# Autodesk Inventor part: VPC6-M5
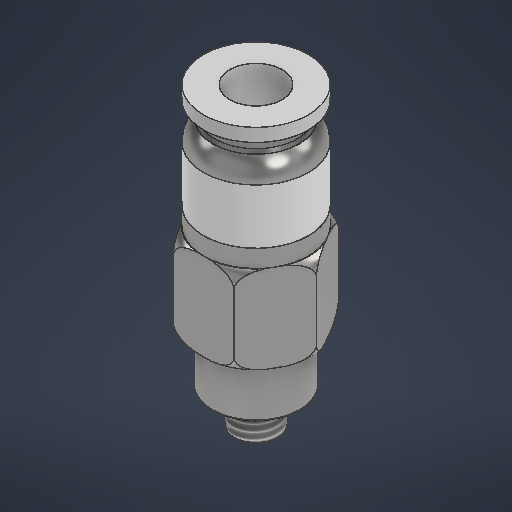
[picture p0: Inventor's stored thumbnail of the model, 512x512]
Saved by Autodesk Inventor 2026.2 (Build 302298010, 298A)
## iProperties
Created: 2026-05
Part Number: VPC6-M5
Material: 스테인리스스틸
Document SubType Name: Modeling
Designer: work
Density: 8 g/cm^3
Appearance: 반연마
Author: work
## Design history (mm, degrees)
sketch "스케치1"
  geometry: C1 r 5 at (0, 0); 1 further point
  constraints: 1 centre point, 1 coincident
  dimensions: "d0" = 10 diameter of C1
extrude "돌출1" new body sketch "스케치1" distance "d1" = 6; taper "d2" = 0 deg
sketch "스케치2"
  geometry: C1 r 2.5 at (0, 0); 1 further point
  constraints: 1 centre point, 1 coincident
  dimensions: "d3" = 5 diameter of C1
extrude "돌출2" join sketch "스케치2" distance "d4" = 4; taper "d5" = 0 deg
feature "스레드1" dims "d6" = 4, "d7" = 0
sketch "스케치3"
  geometry: L1 (-3.464, -6)-(-6.928, 0); L2 (-6.928, 0)-(-3.464, 6); L3 (-3.464, 6)-(3.464, 6); L4 (3.464, 6)-(6.928, 0); L5 (6.928, 0)-(3.464, -6); L6 (3.464, -6)-(-3.464, -6); L7 (0, 0)-(0, -6); 1 further point
  constraints: 14 end point, 1 coincident, 1 midpoint, 1 vertical, 13 other
  dimensions: "d8" = 12 distance between parallel lines of L3 L6
extrude "돌출3" join sketch "스케치3" distance "d9" = 10; taper "d10" = 0 deg
sketch "스케치4"
  geometry: C1 r 6 at (0, 0); 1 further point
  constraints: 1 centre point, 1 coincident
  dimensions: "d11" = 12 diameter of C1
extrude "돌출4" join sketch "스케치4" distance "d12" = 8; taper "d13" = 0 deg
sketch "스케치5"
  geometry: L1 (6, 24)-(-6, 24) reference; L2 (-4.75, 26.75)-(0, 26.75); L3 (0, 26.75)-(0, 24); L4 (-4.75, 26.75)-(-4.75, 27.75); L5 (-4.75, 27.75)-(-3.5, 27.75); L6 (-3.5, 27.75)-(-3.5, 28.5); L7 (-3.5, 28.5)-(-6, 28.5); L8 (-6, 28.5)-(-6, 30); L9 (-6, 30)-(0, 30); L10 (0, 30)-(0, 24); L11 (5, 0)-(-5, 0) reference; L12 (-6, 16)-(-6, 24) reference; A1 r 3.65 centre (-2.35, 24) between (-4.75, 26.75) and (-6, 24); 3 further points
  constraints: 18 end point, 4 perpendicular, 3 midpoint, 2 point on circle, 2 vertical, 1 centre point, 1 horizontal, 1 parallel, 1 point on line, 1 tangent
  dimensions: "d14" = 30 distance between parallel lines of L11 L9; "d15" = 12 diameter of point (-6, 29.25) L10; "d16" = 1.5 distance between parallel lines of L7 L9; "d17" = 9.5 diameter of L4 L10; "d18" = 7 diameter of point (-3.5, 28.125) L10; "d19" = 1 distance of L2.start L4.end; "d20" = 0.75 distance of L5.end L6.end
revolve "회전1" sketch "스케치5" stored, may be unused: angle "d21" = 90 deg
sketch "스케치6"
  geometry: C1 r 2.5 at (0, 0) reference; C2 r 3 at (0, 0); 1 further point
  constraints: 1 centre point, 1 coincident
  dimensions: "d22" = 6 diameter of C2
extrude "돌출5" cut sketch "스케치6" distance "d23" = 8; taper "d24" = 0 deg
node "작업 평면1"
sketch "스케치7"
  geometry: C1 r 5.99 at (0, 0); A1 r 6 centre (0, 0) between (5.196, 3) and (0, 6) reference; 3 further points
  constraints: 2 coincident, 1 centre point, 1 concentric, 3 other
  dimensions: "d26" = 0.01 radial gap between concentric circles of A1 C1
extrude "돌출6" cut sketch "스케치7" distance "d27" = 7; taper "d28" = 0 deg
chamfer "모따기1" distance "d29" = 0.25; stored, may be unused: second distance "d30" = 2, angle "d31" = 45 deg
sketch "스케치8"
  geometry: L1 (6.928, 16)-(5.196, 16) reference; L2 (6.928, 6)-(3.464, 6) reference; L3 (3.464, 6)-(3.464, 16) reference; L4 (5.196, 16)-(3.464, 16) reference; L5 (6.928, 16)-(5.196, 16) reference; L6 (6.928, 6)-(6.928, 16) reference; L7 (6.928, 11)-(0, 11); L8 (0, 16)-(0, 5.389); A1 r 2 centre (4.928, 14.353) between (6.928, 14.353) and (6.062, 16); A2 r 2 centre (4.928, 7.647) between (6.062, 6) and (6.928, 7.647); 5 further points
  constraints: 4 end point, 4 point on circle, 3 symmetric about line, 2 centre point, 2 midpoint, 1 horizontal, 1 parallel, 1 point on line, 1 tangent, 1 vertical, 1 other
  dimensions: "d32" = 2 radius of A1
revolve "회전2" sketch "스케치8" stored, may be unused: angle "d33" = 90 deg
node "솔리드1"
node "투영된 루프1"
feature "A9D066F2-1C7D-4E18-AEED-F7BC21143FA4" dims "d6" = 4, "d7" = 0
other parameters: "d25" = 2
